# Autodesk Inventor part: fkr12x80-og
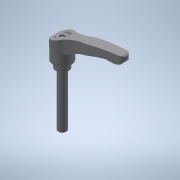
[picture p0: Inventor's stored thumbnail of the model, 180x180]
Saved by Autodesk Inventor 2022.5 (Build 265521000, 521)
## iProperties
Created: 2016-12
Part Number: fkr12x80-og
Material: 一般
Document SubType Name: Modeling
Designer: imaocorp
Density: 1 g/cm^3
Appearance: 既定
Author: imaocorp
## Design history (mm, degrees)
node "fkr12x80-og.x_t1"
node "K1000_412080_012"
node "Base1"
